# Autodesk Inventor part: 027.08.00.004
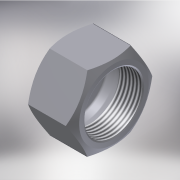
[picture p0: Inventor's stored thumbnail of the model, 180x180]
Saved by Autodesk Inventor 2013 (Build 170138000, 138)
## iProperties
Shininess: 25.0
Length Units: 11269
Angle Units: 11279
Time Units: 11290
Mass Units: 11283
Length Display Precision: 3
Angle Display Precision: 2
Created: 2001-08
Part Number: 027.08.00.004
Document SubType Name: Modeling
Designer: SOleg
Material: Steel, Mild
Density: 7.86 g/cm^3
Density: 0.0
Volumn: 0.0
Area: 0.0
PropertySet Name: Model Information
Control State: 0
Master: False
Checked Out: True
Checked Out Date: 2008-10-15
Last Check In Date: 2008-10-15
Author: SOleg
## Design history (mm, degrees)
node "WorkPlane1"
node "WorkPlane2"
node "WorkPlane6"
node "Sketch1"
node "WorkPoint1"
workplane "Work Plane4"
node "WorkPlane4"
workplane "Work Plane6"
node "WorkPlane7"
sketch "Sketch2"
  geometry: L1 (-23.671, 0)-(-11.836, -20.5); L2 (-11.836, 20.5)-(-23.671, 0); L3 (11.836, 20.5)-(-11.836, 20.5); L4 (23.671, 0)-(11.836, 20.5); L5 (11.836, -20.5)-(23.671, 0); L6 (-11.836, -20.5)-(11.836, -20.5); L7 (0, 0)-(-1, 0)
  constraints: 14 end point, 3 parallel
  dimensions: "d4" = 60 deg angle of L7 L5; "d6" = 41 distance of L5.start L3.start (computed from mdtd1); "d8" = 41 distance of L4.start L2.start (computed from mdtd1); "d10" = 23.67136 distance of L4.start L3.start (computed from mdtd1); "d12" = 23.67136 distance of L1.start L1.end (computed from mdtd1); "d14" = 120 deg angle of L4 L5; "d16" = 120 deg angle of L3 L4; "d18" = 20.5 distance from line of L6 L7.start (computed from mdtd1); "d20" = 23.67136 distance of L4.start L7.start (computed from mdtd1)
extrude "ExtrusionBlind1" new body sketch "Sketch2" distance "d21" = 26 (computed from mdtd10); taper "d22" = 0 deg
node "WorkPlane3"
sketch "Sketch3"
  geometry: L1 (0, 23.671)-(-2.697, 23.671); L2 (0, 23.671)-(0, 19); L3 (-2.697, 23.671)-(0, 19); L4 (-26, 23.671)-(0, 23.671); L5 (0, 0)-(0, 19); L6 (0, 0)-(2, 0); L7 (0, 0)-(2, 0)
  constraints: 14 end point, 3 point on line, 1 horizontal
  dimensions: "d26" = 0 horizontal distance of L5.start L4.end; "d28" = 60 deg angle of L3 L6
revolve "RevolutionAngle1" sketch "Sketch3" stored, may be unused: angle "d29" = 360 deg
sketch "Sketch4"
  geometry: L1 (0, 23.671)-(2.697, 23.671); L2 (0, 23.671)-(0, 19); L3 (2.697, 23.671)-(0, 19); L4 (0, 23.671)-(2.697, 23.671); L5 (0, 0)-(0, 23.671); L6 (0, 0)-(0, 19); L7 (0, 0)-(2, 0); L8 (0, 0)-(2, 0)
  constraints: 16 end point, 3 point on line, 1 horizontal
  dimensions: "d31" = 0 horizontal distance of L5.start L5.end; "d33" = 60 deg angle of L7 L3; "d35" = 19 distance of L6.end L5.start
revolve "RevolutionAngle2" sketch "Sketch4" stored, may be unused: angle "d36" = 360 deg
sketch "Sketch5"
  geometry: L1 (161.449, 165.748)-(161.449, 163.494); L2 (165.971, 166.748)-(162.449, 166.748); L3 (169.449, 165.548)-(166.69, 166.614); L4 (182.449, 166.248)-(182.045, 165.548); L5 (182.449, 149.748)-(182.449, 166.248); L6 (161.449, 149.748)-(182.449, 149.748); L7 (161.449, 163.494)-(161.449, 149.748); L8 (182.449, 149.748)-(182.449, 150.76); L9 (161.449, 149.748)-(182.449, 149.748); L10 (156.449, 168.748)-(156.449, 130.748) reference; L11 (156.449, 149.748)-(198.122, 149.748); L12 (169.449, 165.548)-(182.045, 165.548); A1 r 1 centre (162.449, 165.748) between (162.449, 166.748) and (161.449, 165.748); A2 r 1.993 centre (165.971, 164.754) between (166.69, 166.614) and (165.971, 166.748)
  constraints: 22 end point, 4 point on circle, 4 tangent, 3 vertical, 2 centre point, 2 collinear, 2 parallel, 1 midpoint, 1 point on line
  dimensions: "d38" = 1 radius of A1; "d40" = 13 horizontal distance of L4.start L3.start (computed from mdtd30); "d42" = 21 horizontal distance of L1.start L5.start (computed from mdtd30); "d44" = 30 deg angle of L4 L5; "d46" = 90 deg angle of L6 L7; "d48" = 17 vertical distance of L2.end L6.start; "d50" = 5.24102 horizontal distance of L3.end L1.end; "d52" = 16.5 distance of L4.start L5.start (= 0.1 x mdtd36); "d54" = 13.74582 distance of L1.end L6.start (computed from mdtd36, mdtd38); "d68" = 15.8 distance between parallel lines of L6 L12
revolve "RevolutionAngle3" sketch "Sketch5" stored, may be unused: angle "d57" = 360 deg
node "WorkAxis1"
extrude "ExtrusionBlind2" cut distance "d60" = 8.22323 (computed from mdtd49); taper "d61" = 0 deg
  node "Sketch6" dims "d59" = 26
node "WorkPlane5"
thread "Thread3" dims "d69" = 10, "d70" = 0
body "Solid1"
other parameters: "mdtd36" = 165 [user parameter; used in 2 equation terms], "mdtd38" = 12.2687 [user parameter; used in 1 equation term], "mdtd49" = 82.23227 [user parameter; used in 2 equation terms], "d0" = 0, "d1" = -26 (computed from mdtd10), "d2" = -8.22323 (computed from mdtd49), "d3" = 60 deg (derived), "d5" = 41 (derived), "d7" = 41 (derived), "d9" = 23.67136 (derived), "d11" = 23.67136 (derived), "d13" = 120 deg (derived), "d15" = 120 deg (derived), "d17" = 20.5 (derived), "d19" = 23.67136 (derived), "d23" = 0, "d24" = 0, "d25" = 0 (derived), "d27" = 60 deg (derived), "d30" = 0 (derived), "d32" = 60 deg (derived), "d34" = 19 (derived), "d37" = 1 (derived), "d39" = 13 (derived), "d41" = 21 (derived), "d43" = 30 deg (derived), "d45" = 90 deg (derived), "d47" = 17 (derived), "d49" = 5.24102 (derived), "d51" = 16.5 (derived), "d53" = 13.74582 (derived), "d55" = 150 deg (derived), "d58" = 26 (derived), "d62" = 0, "d63" = 0
